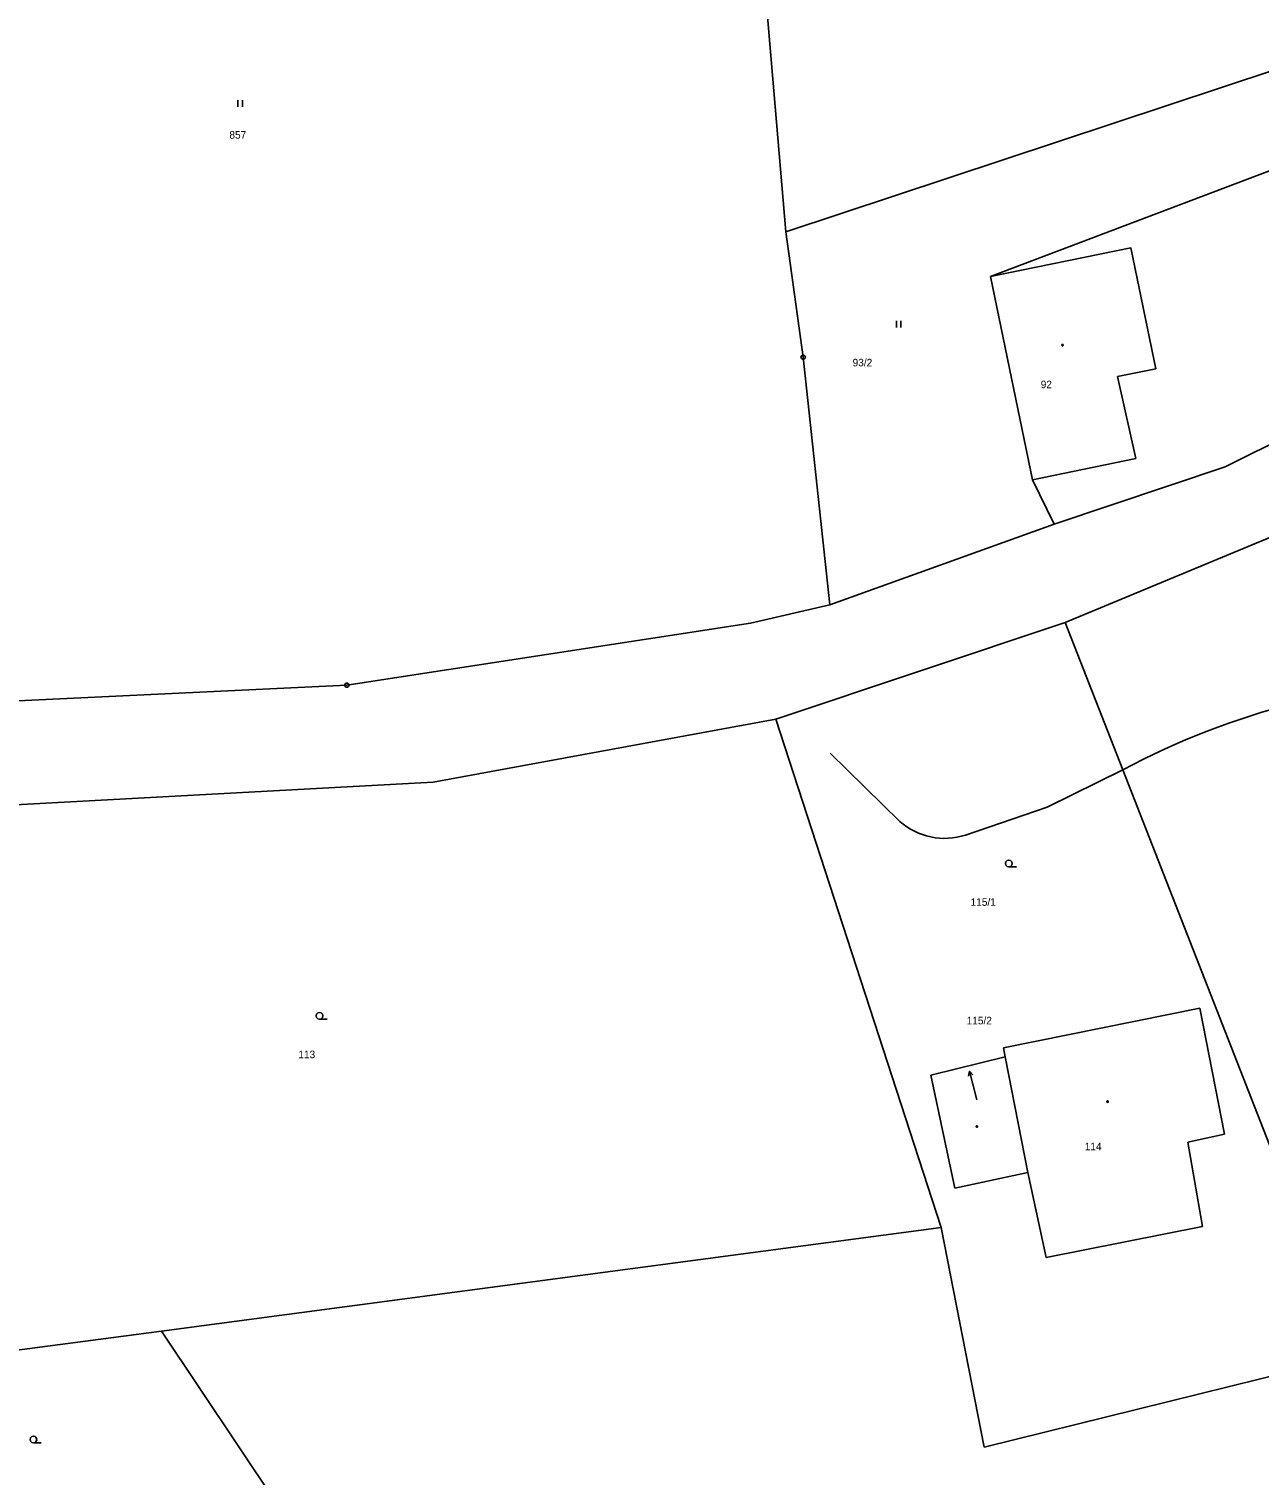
# Model space of a CAD drawing. Extents: x -871430 to -870620, y -1010094 to -1009649.
# Drawn here: x -870892.6 to -870823.3, y -1009857 to -1009775.5 of the extents above; entities that cross this region are included whole.
import ezdxf

# ---------------------------------------------------------------- set-up
doc = ezdxf.new("R2010")
doc.units = 0
for name, color, linetype in [('Vrstva 1', 7, 'Continuous'), ('Vrstva 2', 7, 'Continuous'), ('Vrstva 3', 7, 'Continuous'), ('Vrstva 4', 7, 'Continuous'), ('Vrstva 5', 7, 'Continuous'), ('Vrstva 7', 7, 'Continuous'), ('Vrstva 8', 7, 'Continuous')]:
    doc.layers.add(name, color=color, linetype=linetype)

msp = doc.modelspace()

# ---------------------------------------------------------------- linework, layer by layer
at = {"layer": 'Vrstva 1'}
for p, q in [((-870849.95, -1009786.94), (-870852.48, -1009757.06)), ((-870838.41, -1009789.46), (-870816.52, -1009781.15)), ((-870848.97, -1009794), (-870849.95, -1009786.94)), ((-870836.04, -1009800.91), (-870838.41, -1009789.46)), ((-870847.46, -1009807.96), (-870848.97, -1009794)), ((-870813.03, -1009794.11), (-870825.19, -1009800.18)), ((-870825.19, -1009800.18), (-870834.83, -1009803.41)), ((-870836.04, -1009800.91), (-870834.83, -1009803.41)), ((-870834.83, -1009803.41), (-870847.46, -1009807.96)), ((-870834.21, -1009808.96), (-870819.66, -1009802.91)), ((-870847.46, -1009807.96), (-870851.94, -1009809)), ((-870851.94, -1009809), (-870874.68, -1009812.49)), ((-870850.5, -1009814.41), (-870834.21, -1009808.96)), ((-870830.96, -1009817.26), (-870834.21, -1009808.96)), ((-870874.68, -1009812.49), (-870902.13, -1009813.79)), ((-870869.82, -1009817.95), (-870850.5, -1009814.41)), ((-870850.5, -1009814.41), (-870841.19, -1009843.06)), ((-870821.71, -1009840.91), (-870830.96, -1009817.26)), ((-870928.98, -1009821.19), (-870869.82, -1009817.95)), ((-870826.61, -1009830.7), (-870837.68, -1009832.94)), ((-870825.22, -1009837.8), (-870826.61, -1009830.7)), ((-870837.58, -1009833.45), (-870837.68, -1009832.94)), ((-870841.77, -1009834.48), (-870837.58, -1009833.45)), ((-870837.58, -1009833.45), (-870836.3, -1009839.96)), ((-870841.77, -1009834.48), (-870840.42, -1009840.84)), ((-870827.29, -1009838.26), (-870825.22, -1009837.8)), ((-870826.47, -1009843.01), (-870827.29, -1009838.26)), ((-870840.42, -1009840.84), (-870836.3, -1009839.96)), ((-870836.3, -1009839.96), (-870835.28, -1009844.75)), ((-870841.19, -1009843.06), (-870885.13, -1009848.9)), ((-870841.19, -1009843.06), (-870838.76, -1009855.45)), ((-870835.28, -1009844.75), (-870826.47, -1009843.01)), ((-870885.13, -1009848.9), (-870917.84, -1009853.25)), ((-870878.69, -1009858.54), (-870885.13, -1009848.9)), ((-870838.76, -1009855.45), (-870818.53, -1009850.43))]:
    msp.add_line(p, q, dxfattribs=at)
msp.add_lwpolyline([(-870849.95, -1009786.94), (-870819.21, -1009776.75), (-870816.52, -1009781.15)], dxfattribs=at)
at = {"layer": 'Vrstva 3'}
for p, q in [((-870880.815, -1009779.515), (-870880.815, -1009779.89)), ((-870880.565, -1009779.89), (-870880.565, -1009779.515)), ((-870843.705, -1009791.945), (-870843.705, -1009792.32)), ((-870843.455, -1009792.32), (-870843.455, -1009791.945))]:
    msp.add_line(p, q, dxfattribs=at)
for points in [[(-870837.38, -1009822.73), (-870837.475, -1009822.705), (-870837.542, -1009822.635), (-870837.568, -1009822.542), (-870837.542, -1009822.45), (-870837.475, -1009822.38), (-870837.38, -1009822.355), (-870837.285, -1009822.38), (-870837.218, -1009822.45), (-870837.192, -1009822.542), (-870837.218, -1009822.635), (-870837.285, -1009822.705), (-870837.38, -1009822.73), (-870836.942, -1009822.73)], [(-870876.22, -1009831.32), (-870876.315, -1009831.295), (-870876.382, -1009831.225), (-870876.408, -1009831.132), (-870876.382, -1009831.04), (-870876.315, -1009830.97), (-870876.22, -1009830.945), (-870876.125, -1009830.97), (-870876.058, -1009831.04), (-870876.032, -1009831.132), (-870876.058, -1009831.225), (-870876.125, -1009831.295), (-870876.22, -1009831.32), (-870875.782, -1009831.32)], [(-870892.34, -1009855.2), (-870892.435, -1009855.175), (-870892.502, -1009855.105), (-870892.528, -1009855.012), (-870892.502, -1009854.92), (-870892.435, -1009854.85), (-870892.34, -1009854.825), (-870892.245, -1009854.85), (-870892.178, -1009854.92), (-870892.152, -1009855.012), (-870892.178, -1009855.105), (-870892.245, -1009855.175), (-870892.34, -1009855.2), (-870891.902, -1009855.2)]]:
    msp.add_lwpolyline(points, dxfattribs=at)
at = {"layer": 'Vrstva 4'}
for p, q in [((-870838.41, -1009789.46), (-870830.5, -1009787.83)), ((-870830.5, -1009787.83), (-870829.09, -1009794.65)), ((-870829.09, -1009794.65), (-870831.25, -1009795.09)), ((-870831.25, -1009795.09), (-870830.23, -1009799.71)), ((-870836.04, -1009800.91), (-870830.23, -1009799.71)), ((-870843.52, -1009820.17), (-870847.44, -1009816.33)), ((-870830.96, -1009817.26), (-870835.21, -1009819.36)), ((-870835.21, -1009819.36), (-870839.82, -1009820.94))]:
    msp.add_line(p, q, dxfattribs=at)
for centre, radius, start, end in [((-870810.614, -1009855.369), 43.2, 90.40568, 118.09695), ((-870840.998, -1009817.325), 3.802, 228.44471, 288.04346)]:
    msp.add_arc(centre, radius, start, end, dxfattribs=at)
at = {"layer": 'Vrstva 5'}
for points in [[(-870834.36, -1009793.278), (-870834.335, -1009793.282), (-870834.322, -1009793.305), (-870834.318, -1009793.32), (-870834.322, -1009793.342), (-870834.342, -1009793.36), (-870834.36, -1009793.362), (-870834.382, -1009793.355), (-870834.398, -1009793.34), (-870834.402, -1009793.32), (-870834.398, -1009793.298), (-870834.378, -1009793.28), (-870834.36, -1009793.278)], [(-870831.82, -1009835.928), (-870831.795, -1009835.932), (-870831.782, -1009835.955), (-870831.778, -1009835.97), (-870831.782, -1009835.992), (-870831.802, -1009836.01), (-870831.82, -1009836.012), (-870831.842, -1009836.005), (-870831.857, -1009835.99), (-870831.862, -1009835.97), (-870831.857, -1009835.948), (-870831.837, -1009835.93), (-870831.82, -1009835.928)], [(-870839.18, -1009837.328), (-870839.155, -1009837.332), (-870839.143, -1009837.355), (-870839.138, -1009837.37), (-870839.143, -1009837.392), (-870839.163, -1009837.41), (-870839.18, -1009837.412), (-870839.202, -1009837.405), (-870839.218, -1009837.39), (-870839.222, -1009837.37), (-870839.218, -1009837.348), (-870839.198, -1009837.33), (-870839.18, -1009837.328)]]:
    msp.add_lwpolyline(points, dxfattribs=at)
at = {"layer": 'Vrstva 7'}
for p in [(-870839.598, -1009834.254), (-870839.18, -1009835.87)]:
    msp.add_line(p, (-870839.41, -1009834.98), dxfattribs=at)
msp.add_lwpolyline([(-870839.656, -1009834.527), (-870839.598, -1009834.254), (-870839.414, -1009834.465)], dxfattribs=at)
at = {"layer": 'Vrstva 8'}
for p, q in [((-870848.982, -1009794), (-870848.958, -1009794)), ((-870874.692, -1009812.49), (-870874.668, -1009812.49))]:
    msp.add_line(p, q, dxfattribs=at)
for points in [[(-870848.932, -1009793.88), (-870848.87, -1009793.928), (-870848.845, -1009794), (-870848.87, -1009794.072), (-870848.932, -1009794.12), (-870849.008, -1009794.12), (-870849.07, -1009794.072), (-870849.095, -1009794), (-870849.07, -1009793.928), (-870849.008, -1009793.88), (-870848.932, -1009793.88)], [(-870874.643, -1009812.37), (-870874.58, -1009812.418), (-870874.555, -1009812.49), (-870874.58, -1009812.562), (-870874.643, -1009812.61), (-870874.718, -1009812.61), (-870874.78, -1009812.562), (-870874.805, -1009812.49), (-870874.78, -1009812.418), (-870874.718, -1009812.37), (-870874.643, -1009812.37)]]:
    msp.add_lwpolyline(points, dxfattribs=at)

# ---------------------------------------------------------------- texts
at = {"layer": 'Vrstva 2'}
for s, height, p in [('857', 0.425, (-870881.299, -1009781.682)), ('93/2', 0.425, (-870846.181, -1009794.52)), ('92', 0.425, (-870835.581, -1009795.75)), ('115/1', 0.425, (-870839.532, -1009824.93)), ('113', 0.425, (-870877.412, -1009833.52)), ('115/2', 0.025, (-870839.174, -1009835.87)), ('114', 0.425, (-870833.102, -1009838.71))]:
    msp.add_text(s, height=height, dxfattribs=at).set_placement(p)
at = {"layer": 'Vrstva 7'}
msp.add_text('115/2', height=0.425, dxfattribs=at).set_placement((-870839.756, -1009831.61))

doc.saveas('drawing.dxf')
